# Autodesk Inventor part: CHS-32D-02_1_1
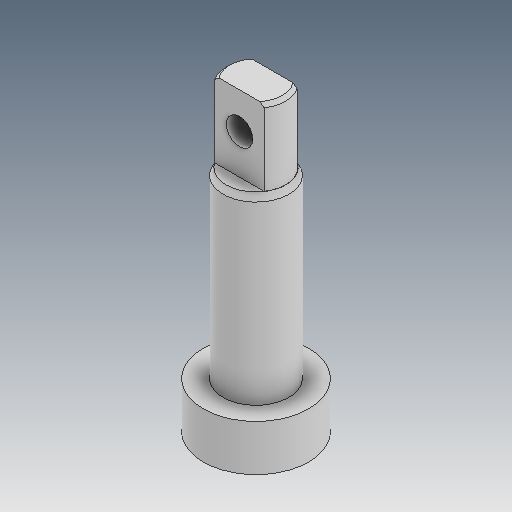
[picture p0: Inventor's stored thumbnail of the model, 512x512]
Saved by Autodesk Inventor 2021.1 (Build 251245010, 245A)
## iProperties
Created: 2019-04
Part Number: CHS-32D-02_1_1
Material: Ogólny
Document SubType Name: Modeling
Designer: user
Density: 1 g/cm^3
Appearance: Domyślna
Author: user
Revision Number: ÈÎºÎ
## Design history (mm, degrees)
feature "ÊäÈë1"
feature "ÊäÈë2"
node "Bryła1"
node "Bryła2"
